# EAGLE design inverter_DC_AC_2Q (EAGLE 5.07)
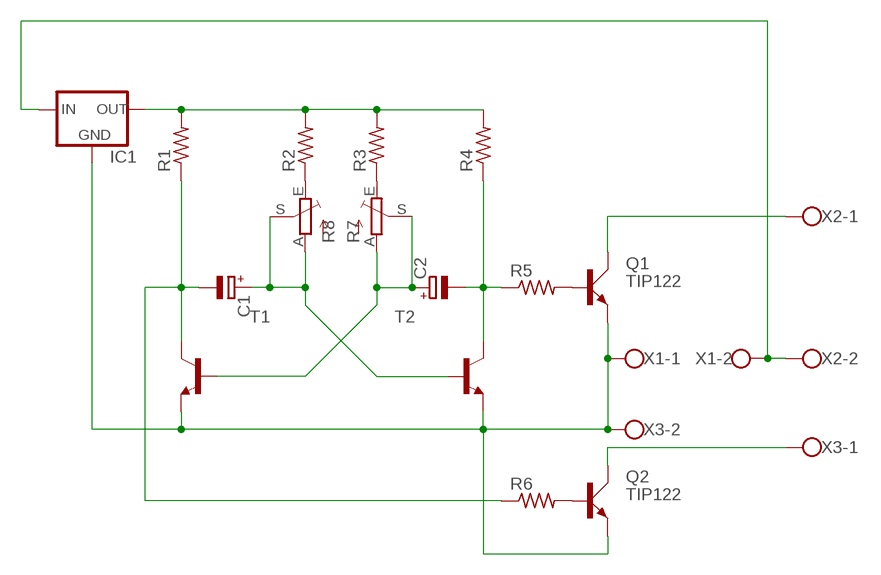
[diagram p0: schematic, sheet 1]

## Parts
C1  CPOL-EUE5-6  [E5-6]
C2  CPOL-EUE5-6  [E5-6]
IC1  78XXS  [78XXS]
Q1  TIP122  TIP41C  [TO220AV]
Q2  TIP122  TIP41C  [TO220AV]
R1  R-US_0207/10  [0207/10]
R2  R-US_0207/10  [0207/10]
R3  R-US_0207/10  [0207/10]
R4  R-US_0207/10  [0207/10]
R5  R-US_0207/10  [0207/10]
R6  R-US_0207/10  [0207/10]
R7  TRIM_EU-CA14H  [CA14H]
R8  TRIM_EU-CA14H  [CA14H]
T1  BC337-NPN-TO92-EBC  [TO92-EBC]
T2  BC337-NPN-TO92-EBC  [TO92-EBC]
X1  W237-102  [W237-102]
X2  W237-102  [W237-102]
X3  W237-102  [W237-102]

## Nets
N$1: C1.+ R7.A R7.S T2.B
N$2: C2.+ R8.A R8.S T1.B
N$4: C2.- R4.1 R5.1 T2.C
N$5: R3.1 R8.E
N$6: IC1.GND Q1.E Q2.E T1.E T2.E X1.1 X3.2
N$7: C1.- R1.1 R6.1 T1.C
N$8: IC1.OUT R1.2 R2.2 R3.2 R4.2
N$9: Q1.B R5.2
N$10: Q2.B R6.2
N$11: IC1.IN X1.2 X2.2
N$12: R2.1 R7.E
N$14: Q1.C X2.1
N$15: Q2.C X3.1

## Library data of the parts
C1 C2 = resistor:CPOL-EU: POLARIZED CAPACITOR, European symbol
IC1 = v-reg:78XXS: VOLTAGE REGULATOR
Q1 Q2 = transistor-power:TIP41C: NPN TRANSISTOR
R1-R6 = resistor:R-US_: RESISTOR, American symbol
R7 R8 = pot:TRIM_EU-: POTENTIOMETER
T1 T2 = transistor:*-NPN-: NPN Transistror BF959 corrected 2008.03.06
X1-X3 = con-wago-500:W237-102: WAGO SCREW CLAMP

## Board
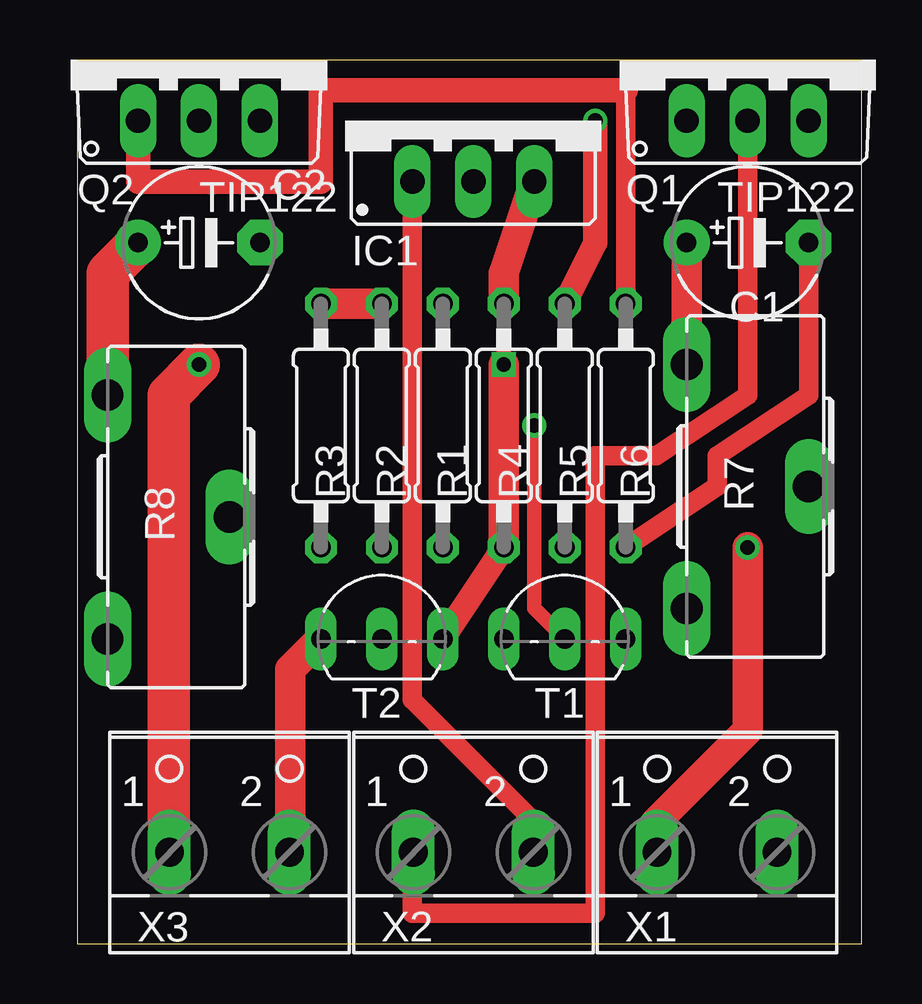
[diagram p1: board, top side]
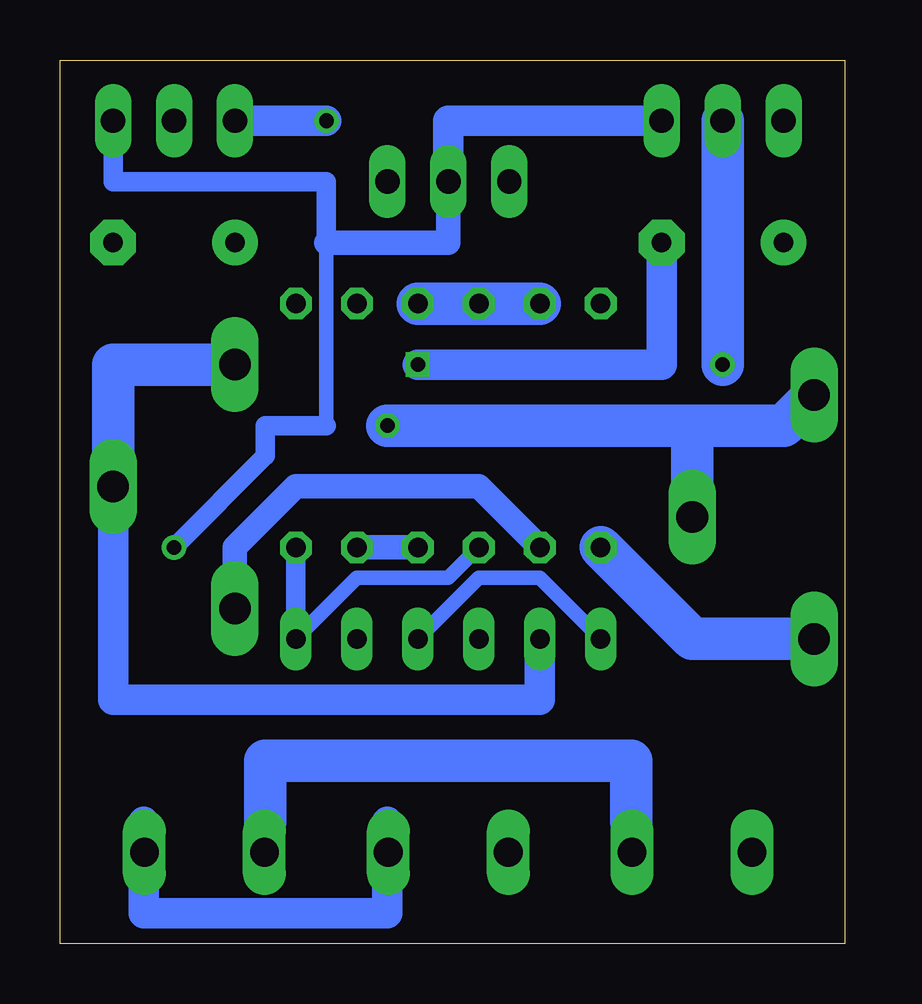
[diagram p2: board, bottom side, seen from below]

Size 32.69 x 36.82 mm. Coordinates in mm from the lower left corner, seen from the top.
Outline: 0,0 32.69,0 32.69,36.82 0,36.82 0,0
Copper layers (1*16): Top 0.035mm / dielectric 1.5mm / Bottom 0.035mm
Design rules "default": minimum track width 10mil, minimum drill 24mil, track to track 8mil, track to pad 8mil, pad to pad 8mil, via to via 8mil, smd to smd 8mil, copper to edge 40mil, drill to drill 8mil, minimum pad ring 10mil, minimum via ring 8mil, stop-mask expansion 4mil, vias tented up to drill 0mil, thermal gap 10mil

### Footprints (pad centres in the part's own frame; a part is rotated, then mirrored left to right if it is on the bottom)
E5-6 = drill 0.813 pad 1.905 round: + -2.54,0 | drill 0.813 pad 1.905 octagon: - 2.54,0
78XXS = drill 1.016 long: GND 0,-2.54; IN -2.54,-2.54; OUT 2.54,-2.54
TO220AV = drill 1.016 long: B -2.54,-2.54; C 0,-2.54; E 2.54,-2.54
0207/10 = drill 0.813 octagon: 1 -5.08,0; 2 5.08,0
CA14H = drill 1.321 long: A -5.08,0; E 5.08,0; S 0,5.08
TO92-EBC = drill 0.813 long: B 0,-1.27; C 2.54,-1.27; E -2.54,-1.27
W237-102 = drill 1.194 long: 1 -2.5,-1.27; 2 2.5,-1.27

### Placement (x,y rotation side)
C1  27.94,29.21 0 top
C2  5.08,29.21 0 top
IC1  16.51,34.29 0 top
Q1  27.94,36.83 0 top
Q2  5.08,36.83 0 top
R1  15.24,21.59 90 top
R2  12.7,21.59 90 top
R3  10.16,21.59 90 top
R4  17.78,21.59 90 top
R5  20.32,21.59 90 top
R6  22.86,21.59 90 top
R7  25.4,19.05 270 top
R8  1.27,17.78 270 top
T1  20.32,13.97 0 top
T2  12.7,13.97 0 top
X1  26.67,5.08 0 top
X2  16.51,5.08 0 top
X3  6.35,5.08 0 top

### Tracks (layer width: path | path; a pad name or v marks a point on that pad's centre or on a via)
N$1
  Top 1.27: R7.A C1.+
  Bottom 1.27: T2.B 12.7,10.16 30.48,10.16 R7.S
  Bottom 1.778: R7.S 30.48,24.13 R7.A
N$2  (via drill 0.61)
  Top 0.61: T1.B 19.05,13.97 v19.05,21.59
  Top 1.778: C2.+ 1.27,27.94 R8.A
  Bottom 1.778: R8.A 2.54,21.59 6.35,21.59 | 6.35,21.59 v19.05,21.59 | R8.S 6.35,21.59
N$4  (via drill 0.6)
  Top 1.016: T2.C R4.1
  Top 1.27: R4.1 v17.78,24.13
  Bottom 1.016: R4.1 R5.1
  Bottom 1.27: C2.- 7.62,24.13 v17.78,24.13
N$5
  Bottom 1.778: R3.1 6.35,12.7 R8.E
N$6  (via drill 0.61)
  Top 0.254: X3.2 8.89,5.08
  Top 0.813: X1.1 24.13,5.08
  Top 1.27: T2.E 8.89,11.43 8.89,5.08 | 24.13,5.08 27.94,8.89 v27.94,16.51
  Bottom 0.254: 24.13,5.08 X1.1
  Bottom 0.61: T1.E 15.24,15.24 12.7,15.24 T2.E | 21.59,21.59 21.59,29.21
  Bottom 0.813: Q1.E 30.48,31.75 21.59,31.75 21.59,29.21 | v27.94,16.51 24.13,20.32 24.13,21.59 21.59,21.59
  Bottom 1.016: IC1.GND 16.51,29.21 21.59,29.21
  Bottom 1.27: X3.2 8.89,5.08 | IC1.GND 16.51,34.29 Q2.E
  Bottom 1.778: 24.13,5.08 24.13,7.62 8.89,7.62 8.89,5.08
N$7
  Top 0.813: R6.1 26.67,19.05 26.67,20.32 30.48,22.86 C1.-
  Bottom 0.61: R1.1 16.51,15.24 20.32,15.24 T1.C
  Bottom 0.813: T1.C R6.1
N$8
  Top 1.27: R3.2 R2.2 | IC1.OUT 17.78,27.94 R4.2
  Bottom 1.778: R2.2 R1.2 R4.2
N$9  (via drill 0.61)
  Top 1.016: R5.2 21.59,29.21 v21.59,34.29
  Bottom 1.27: v21.59,34.29 Q1.B
N$10
  Top 0.813: 22.86,35.56 R6.2
  Top 1.016: 22.86,35.56 10.16,35.56 10.16,31.75 2.54,31.75 Q2.B
N$11
  Top 0.254: X2.2 19.05,5.08
  Top 0.813: IC1.IN 13.97,10.16 19.05,5.08
  Bottom 0.254: 29.21,5.08 X1.2
  Bottom 0.61: X2.2 19.05,5.08
  Bottom 1.27: 29.21,5.08 29.21,1.27 19.05,1.27 19.05,5.08
N$12
  Bottom 1.016: R2.1 15.24,19.05 22.86,19.05 25.4,16.51 R7.E
N$14
  Top 0.254: 13.97,5.08 X2.1
  Top 0.813: Q1.C 27.94,22.86 24.13,20.32 21.59,20.32 21.59,1.27 13.97,1.27 13.97,5.08
N$15  (via drill 0.61)
  Top 1.27: X3.1 3.81,5.08
  Top 1.778: v5.08,24.13 3.81,22.86 3.81,5.08
  Bottom 1.778: v5.08,24.13 Q2.C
